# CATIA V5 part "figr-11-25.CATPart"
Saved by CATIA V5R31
Part number: Part1
Bounding box of the stored display mesh (mm): x -89.703 to 75.958, y -127.286 to 108.862, z -26.487 to 19.815
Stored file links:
  D:\PROJECTS\Project 2021\US EDITION\CATIA V5 6R 2021\Resources\Part Files\c11_catia_v5_6r2021_prt\figr-11-25.CATPart
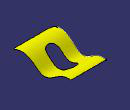
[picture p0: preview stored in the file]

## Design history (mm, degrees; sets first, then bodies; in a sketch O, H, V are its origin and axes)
Set1
  Extrude1: Element1 Sketch3, Lim1 86, Lim2 94, Direction yz-plane
  Sketch1 on xy-plane, origin (0, 0, 0), H (1, 0, 0), V (0, 1, 0)
    line L1 (64.3059, 108.8616) -> (75.9293, -106.0218)
    arc A1 centre (55.7837, -107.1115) radius 20.175 from (75.9293, -106.0218) to (55.7837, -127.2865) cw
    line L2 (55.7837, -127.2865) -> (-64.7868, -127.2865)
    arc A2 centre (-64.7868, -102.3613) radius 24.9252 from (-64.7868, -127.2865) to (-89.6873, -101.2501) cw
    line L3 (-89.6873, -101.2501) -> (-80.3115, 108.8616)
    line L4 (-80.3115, 108.8616) -> (64.3059, 108.8616)
    tangency: A1 L1, A2 L2, A2 L3, A1 L2
    horizontal: L2 H, L4 H
  Extrude2: Element1 Sketch1, Lim1 86, Lim2 94, Direction xy-plane
  Split1: ToCut Extrude1, Cutting Extrude2
  Sketch2 on xy-plane, origin (0, 0, 0), H (1, 0, 0), V (0, 1, 0)
    construction line L1 (-11.3849, 28.4134) -> (-11.3849, -36.9379)
    line L2 (12.8382, 28.4134) -> (12.8382, -36.9379)
    line L3 (-35.608, -36.9379) -> (-35.608, 28.4134)
    arc A1 centre (-11.3849, -36.9379) radius 24.2231 from (12.8382, -36.9379) to (-35.608, -36.9379) cw
    arc A2 centre (-11.3849, 28.4134) radius 24.2231 from (-35.608, 28.4134) to (12.8382, 28.4134) cw
    vertical: L1 V
    tangency: A1 L2, A2 L2, A1 L3, A2 L3
    parallelism: L1 L2
  Extrude3: Element1 Sketch2, Lim1 86, Lim2 94, Direction xy-plane
  Split2: ToCut Split1, Cutting Extrude3
  Boundary1: Boundary edge of Split2, Support Split2
Body1 (main body)
  Sketch3 on yz-plane, origin (0, 0, 0), H (0, 1, 0), V (0, 0, 1)
    spline S1 through (-130.9721, 0) (-85.5087, 19.8151) (-38.0512, 0) (0, -25.6483) (60.0541, -1.7202) (134.7951, -4.3868)
    point P1 (-130.9721, 0)
    point P2 (-38.0512, 0)
    point P3 (0, -25.6483)
    coincidence: P1 H, P2 H, P3 V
